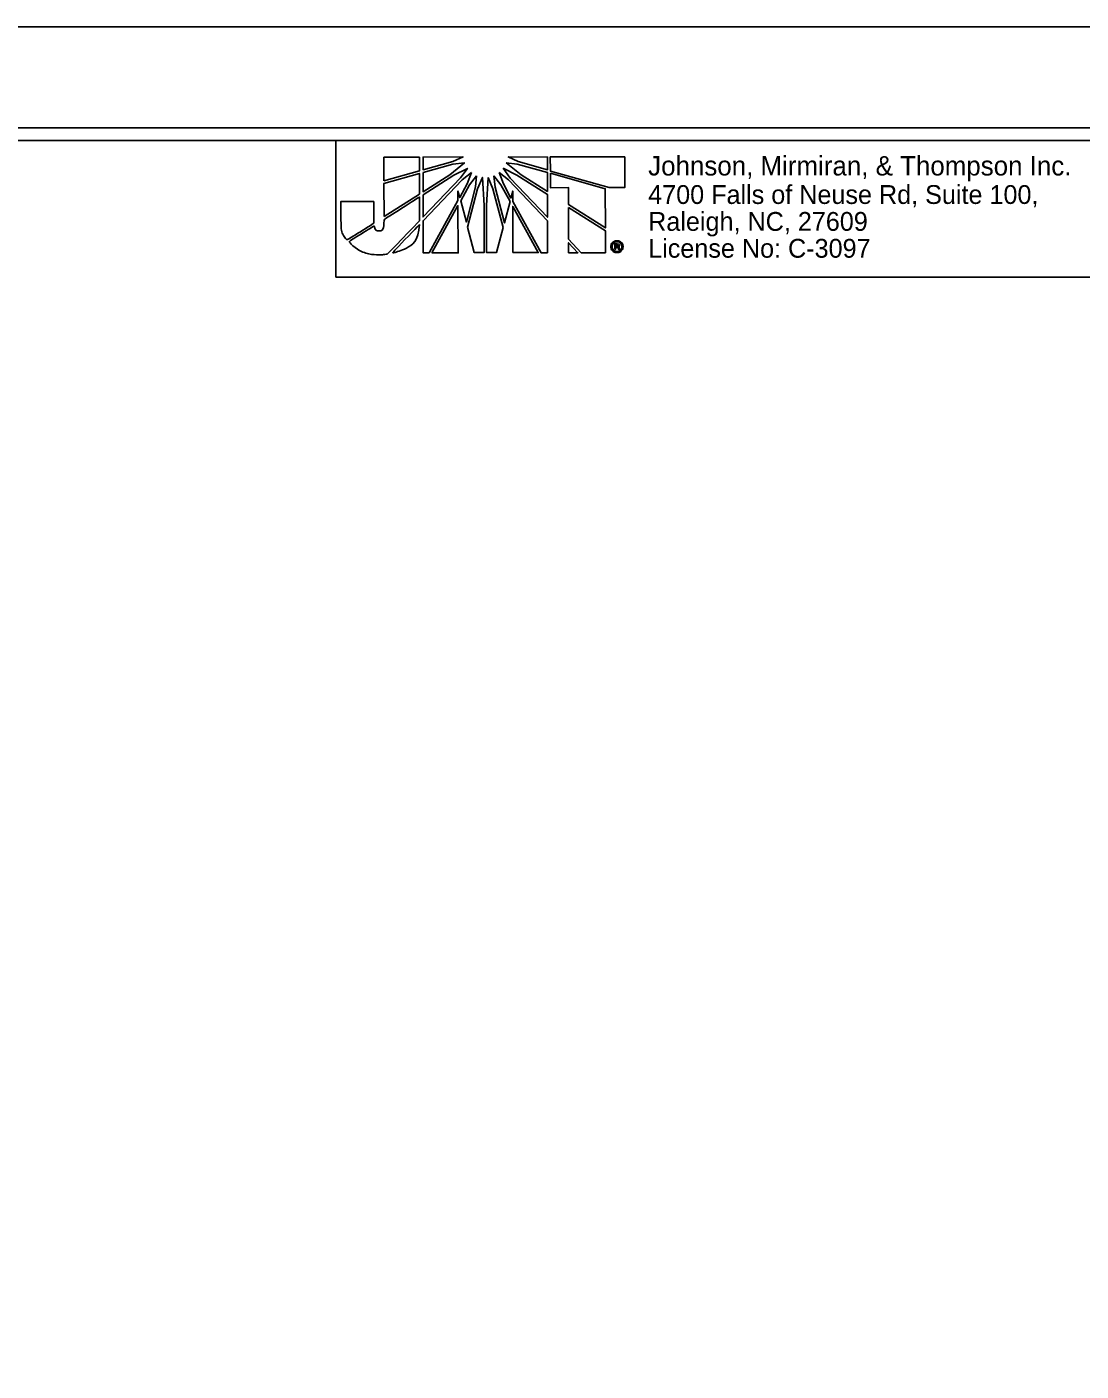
# Model space of a CAD drawing. Extents: x 1639431 to 1642602, y 841916 to 843940.
# Drawn here: x 1641459.6 to 1641668.2, y 842745.3 to 843011.3 of the extents above; entities that cross this region are included whole.
import ezdxf

# ---------------------------------------------------------------- set-up
doc = ezdxf.new("R2010")
doc.units = 0
for name, color, linetype in [('Prop Dimension Text', 7, 'Continuous'), ('Sheet Plan CELL', 7, 'Continuous'), ('Sheet Plot Border Inside CELL', 7, 'Continuous'), ('Sheet Plot Border Outside CELL', 7, 'Continuous')]:
    doc.layers.add(name, color=color, linetype=linetype)

msp = doc.modelspace()

# ---------------------------------------------------------------- linework, layer by layer
at = {"layer": 'Prop Dimension Text'}
for p, q in [((1641537.24, 842985.52), (1641530.22, 842985.51)), ((1641530.22, 842985.51), (1641530.22, 842980.85)), ((1641537.24, 842982.81), (1641537.24, 842985.52)), ((1641545.87, 842985.56), (1641537.97, 842985.55)), ((1641537.97, 842985.55), (1641537.97, 842983.04)), ((1641543.86, 842984.67), (1641545.87, 842985.56)), ((1641562.6, 842985.54), (1641554.81, 842985.57)), ((1641554.81, 842985.57), (1641556.79, 842984.64)), ((1641562.6, 842983.02), (1641562.6, 842985.54)), ((1641577.91, 842985.59), (1641563.14, 842985.58)), ((1641563.14, 842985.58), (1641563.15, 842982.87)), ((1641577.91, 842979.54), (1641577.91, 842985.59)), ((1641530.22, 842980.85), (1641537.24, 842982.81)), ((1641537.97, 842983.04), (1641543.86, 842984.67)), ((1641543.86, 842984.12), (1641537.97, 842982.49)), ((1641537.97, 842982.49), (1641537.98, 842978.69)), ((1641543.24, 842982.04), (1641546.15, 842984.4)), ((1641546.15, 842984.4), (1641543.86, 842984.12)), ((1641546.73, 842983.31), (1641544.06, 842981.95)), ((1641545.38, 842981.41), (1641546.73, 842983.31)), ((1641547.54, 842982.47), (1641545.68, 842981.03)), ((1641546.69, 842980.22), (1641547.54, 842982.47)), ((1641552.99, 842982.47), (1641553.85, 842980.23)), ((1641554.85, 842981.04), (1641552.99, 842982.47)), ((1641553.81, 842983.32), (1641555.17, 842981.39)), ((1641556.52, 842981.97), (1641553.81, 842983.32)), ((1641554.42, 842984.41), (1641557.37, 842982)), ((1641556.59, 842984.13), (1641554.42, 842984.41)), ((1641562.6, 842982.48), (1641556.59, 842984.13)), ((1641556.79, 842984.64), (1641562.6, 842983.02)), ((1641562.56, 842978.76), (1641562.6, 842982.48)), ((1641563.15, 842982.87), (1641563.15, 842982.78)), ((1641563.15, 842982.78), (1641574.77, 842979.54)), ((1641537.24, 842982.3), (1641530.22, 842980.32)), ((1641530.22, 842980.32), (1641530.23, 842973.77)), ((1641537.25, 842978.23), (1641537.24, 842982.3)), ((1641537.98, 842978.69), (1641543.24, 842982.04)), ((1641544.06, 842981.95), (1641537.98, 842978.08)), ((1641537.98, 842973.7), (1641545.38, 842981.41)), ((1641545.68, 842981.03), (1641537.98, 842972.96)), ((1641545.22, 842977.54), (1641546.69, 842980.22)), ((1641547.16, 842980.06), (1641545.42, 842976.88)), ((1641548.55, 842981.84), (1641547.16, 842980.06)), ((1641548.36, 842979.68), (1641548.55, 842981.84)), ((1641549.71, 842981.53), (1641548.75, 842979.28)), ((1641550.02, 842975.99), (1641549.71, 842981.53)), ((1641550.87, 842981.53), (1641550.51, 842975.99)), ((1641551.8, 842979.29), (1641550.87, 842981.53)), ((1641551.99, 842981.85), (1641552.23, 842979.6)), ((1641553.35, 842980.06), (1641551.99, 842981.85)), ((1641555.17, 842976.78), (1641553.35, 842980.06)), ((1641553.85, 842980.23), (1641555.36, 842977.44)), ((1641562.57, 842972.91), (1641554.85, 842981.04)), ((1641555.17, 842981.39), (1641562.57, 842973.64)), ((1641562.56, 842978.14), (1641556.52, 842981.97)), ((1641557.37, 842982), (1641562.56, 842978.76)), ((1641563.15, 842982.37), (1641563.15, 842982.32)), ((1641574.03, 842979.27), (1641563.15, 842982.37)), ((1641563.15, 842982.32), (1641563.15, 842979.49)), ((1641530.23, 842973.77), (1641537.25, 842978.23)), ((1641537.98, 842978.08), (1641537.98, 842973.7)), ((1641544.87, 842976.96), (1641544.87, 842978.82)), ((1641544.87, 842978.82), (1641545.22, 842977.54)), ((1641546.54, 842972.67), (1641548.36, 842979.68)), ((1641548.75, 842979.28), (1641546.78, 842971.69)), ((1641553.82, 842971.58), (1641551.8, 842979.29)), ((1641552.23, 842979.6), (1641554.05, 842972.51)), ((1641555.36, 842977.44), (1641555.71, 842978.83)), ((1641555.71, 842978.83), (1641555.72, 842976.78)), ((1641562.57, 842973.64), (1641562.56, 842978.14)), ((1641563.15, 842979.49), (1641566.75, 842979.5)), ((1641566.75, 842979.5), (1641566.76, 842976.13)), ((1641574.04, 842971.52), (1641574.03, 842979.27)), ((1641574.77, 842979.54), (1641577.91, 842979.54)), ((1641539.15, 842966.59), (1641544.87, 842976.96)), ((1641544.87, 842975.95), (1641539.69, 842966.59)), ((1641544.93, 842966.59), (1641544.87, 842975.95)), ((1641545.42, 842976.88), (1641546.54, 842972.67)), ((1641550.02, 842966.63), (1641550.02, 842975.99)), ((1641550.51, 842975.99), (1641550.52, 842966.63)), ((1641554.05, 842972.51), (1641555.17, 842976.78)), ((1641555.72, 842976.78), (1641561.33, 842966.61)), ((1641560.75, 842966.64), (1641555.72, 842975.77)), ((1641555.72, 842975.77), (1641555.73, 842966.64)), ((1641566.76, 842976.13), (1641574.04, 842971.52)), ((1641566.76, 842975.55), (1641566.76, 842969.27)), ((1641574.04, 842970.98), (1641566.76, 842975.55)), ((1641537.98, 842972.96), (1641537.99, 842966.59)), ((1641562.57, 842966.61), (1641562.57, 842972.91)), ((1641546.78, 842971.69), (1641548.1, 842966.63)), ((1641552.47, 842966.64), (1641553.82, 842971.58)), ((1641566.76, 842969.27), (1641569.28, 842966.62)), ((1641574.04, 842966.62), (1641574.04, 842970.98)), ((1641537.99, 842966.59), (1641539.15, 842966.59)), ((1641539.69, 842966.59), (1641544.93, 842966.59)), ((1641548.1, 842966.63), (1641550.02, 842966.63)), ((1641550.52, 842966.63), (1641552.47, 842966.64)), ((1641555.73, 842966.64), (1641560.75, 842966.64)), ((1641561.33, 842966.61), (1641562.57, 842966.61)), ((1641568.59, 842966.62), (1641566.76, 842968.58)), ((1641566.76, 842968.58), (1641566.77, 842966.61)), ((1641566.77, 842966.61), (1641568.59, 842966.62)), ((1641569.28, 842966.62), (1641574.04, 842966.62)), ((1641575.89, 842967.29), (1641575.89, 842968.36)), ((1641575.89, 842968.36), (1641576.33, 842968.36)), ((1641576.13, 842967.29), (1641575.89, 842967.29)), ((1641576.33, 842968.15), (1641576.13, 842968.15)), ((1641576.13, 842968.15), (1641576.13, 842967.9)), ((1641576.13, 842967.9), (1641576.33, 842967.9)), ((1641576.33, 842967.71), (1641576.13, 842967.71)), ((1641576.13, 842967.71), (1641576.13, 842967.29)), ((1641576.33, 842968.99), (1641576.33, 842968.77)), ((1641576.33, 842968.77), (1641576.33, 842968.99)), ((1641576.33, 842968.36), (1641576.33, 842968.15)), ((1641576.33, 842968.15), (1641576.33, 842968.36)), ((1641576.33, 842968.36), (1641576.4, 842968.36)), ((1641576.36, 842968.15), (1641576.33, 842968.15)), ((1641576.33, 842967.9), (1641576.33, 842967.71)), ((1641576.33, 842967.71), (1641576.33, 842967.9)), ((1641576.33, 842967.9), (1641576.34, 842967.9)), ((1641576.34, 842967.71), (1641576.33, 842967.71)), ((1641576.33, 842966.87), (1641576.33, 842966.63)), ((1641576.33, 842966.63), (1641576.33, 842966.87)), ((1641576.33, 842966.87), (1641576.34, 842966.87)), ((1641576.34, 842966.63), (1641576.33, 842966.63))]:
    msp.add_line(p, q, dxfattribs=at)
msp.add_lwpolyline([(1641520.72, 842961.76), (1641670.75, 842961.76), (1641670.75, 842988.83), (1641520.72, 842988.83)], close=True, dxfattribs=at)
for points in [[(1641530.22, 842980.85), (1641537.24, 842982.81), (1641537.24, 842985.52), (1641530.22, 842985.51), (1641530.22, 842980.85)], [(1641543.86, 842984.67), (1641545.87, 842985.56), (1641537.97, 842985.55), (1641537.97, 842983.04), (1641543.86, 842984.67)], [(1641556.79, 842984.64), (1641562.6, 842983.02), (1641562.6, 842985.54), (1641554.81, 842985.57), (1641556.79, 842984.64)], [(1641577.91, 842985.59), (1641563.14, 842985.58), (1641563.15, 842982.87), (1641563.15, 842982.78), (1641574.77, 842979.54), (1641577.91, 842979.54), (1641577.91, 842985.59)], [(1641537.97, 842982.49), (1641537.98, 842978.69), (1641543.24, 842982.04), (1641546.15, 842984.4), (1641543.86, 842984.12), (1641537.97, 842982.49)], [(1641537.98, 842978.08), (1641537.98, 842973.7), (1641545.38, 842981.41), (1641546.73, 842983.31), (1641544.06, 842981.95), (1641537.98, 842978.08)], [(1641547.54, 842982.47), (1641545.68, 842981.03), (1641537.98, 842972.96), (1641537.99, 842966.59), (1641539.15, 842966.59), (1641544.87, 842976.96), (1641544.87, 842978.82), (1641545.22, 842977.54), (1641546.69, 842980.22), (1641547.54, 842982.47)], [(1641552.99, 842982.47), (1641553.85, 842980.23), (1641555.36, 842977.44), (1641555.71, 842978.83), (1641555.72, 842976.78), (1641561.33, 842966.61), (1641562.57, 842966.61), (1641562.57, 842972.91), (1641554.85, 842981.04), (1641552.99, 842982.47)], [(1641553.81, 842983.32), (1641555.17, 842981.39), (1641562.57, 842973.64), (1641562.56, 842978.14), (1641556.52, 842981.97), (1641553.81, 842983.32)], [(1641554.42, 842984.41), (1641557.37, 842982), (1641562.56, 842978.76), (1641562.6, 842982.48), (1641556.59, 842984.13), (1641554.42, 842984.41)], [(1641530.23, 842973.77), (1641537.25, 842978.23), (1641537.24, 842982.3), (1641530.22, 842980.32), (1641530.23, 842973.77)], [(1641548.55, 842981.84), (1641547.16, 842980.06), (1641545.42, 842976.88), (1641546.54, 842972.67), (1641548.36, 842979.68), (1641548.55, 842981.84)], [(1641548.75, 842979.28), (1641546.78, 842971.69), (1641548.1, 842966.63), (1641550.02, 842966.63), (1641550.02, 842975.99), (1641549.71, 842981.53), (1641548.75, 842979.28)], [(1641550.87, 842981.53), (1641550.51, 842975.99), (1641550.52, 842966.63), (1641552.47, 842966.64), (1641553.82, 842971.58), (1641551.8, 842979.29), (1641550.87, 842981.53)], [(1641551.99, 842981.85), (1641552.23, 842979.6), (1641554.05, 842972.51), (1641555.17, 842976.78), (1641553.35, 842980.06), (1641551.99, 842981.85)], [(1641563.15, 842982.37), (1641563.15, 842982.32), (1641563.15, 842979.49), (1641566.75, 842979.5), (1641566.76, 842976.13), (1641574.04, 842971.52), (1641574.03, 842979.27), (1641563.15, 842982.37)], [(1641539.69, 842966.59), (1641544.93, 842966.59), (1641544.87, 842975.95), (1641539.69, 842966.59)], [(1641555.73, 842966.64), (1641560.75, 842966.64), (1641555.72, 842975.77), (1641555.73, 842966.64)], [(1641566.76, 842975.55), (1641566.76, 842969.27), (1641569.28, 842966.62), (1641574.04, 842966.62), (1641574.04, 842970.98), (1641566.76, 842975.55), (1641566.76, 842975.55)], [(1641566.77, 842966.61), (1641566.77, 842966.61), (1641568.59, 842966.62), (1641566.76, 842968.58), (1641566.77, 842966.61)], [(1641576.8, 842967.54), (1641576.8, 842967.48), (1641576.81, 842967.44), (1641576.81, 842967.4), (1641576.84, 842967.29), (1641576.61, 842967.29)]]:
    msp.add_lwpolyline(points, dxfattribs=at)
for points, degree in [([(1641529.22, 842970.93), (1641528.81, 842970.93), (1641528.45, 842971.17), (1641528.3, 842971.94), (1641528.3, 842971.94), (1641523.26, 842968.82), (1641523.26, 842968.82), (1641524.81, 842967.19), (1641527.29, 842966.22), (1641529.39, 842966.22), (1641529.94, 842966.22), (1641530.35, 842966.27), (1641530.93, 842966.38), (1641530.93, 842966.38), (1641537.25, 842972.92), (1641537.25, 842972.92), (1641537.25, 842972.92), (1641537.25, 842977.65), (1641537.25, 842977.65), (1641537.25, 842977.65), (1641530.23, 842973.18), (1641530.23, 842973.18), (1641530.23, 842971.41), (1641529.8, 842970.93), (1641529.22, 842970.93)], 3), ([(1641529.22, 842970.93), (1641528.81, 842970.93), (1641528.45, 842971.17), (1641528.3, 842971.94), (1641528.3, 842971.94), (1641523.26, 842968.82), (1641523.26, 842968.82), (1641524.81, 842967.19), (1641527.29, 842966.22), (1641529.39, 842966.22), (1641529.94, 842966.22), (1641530.35, 842966.27), (1641530.93, 842966.38), (1641530.93, 842966.38), (1641537.25, 842972.92), (1641537.25, 842972.92), (1641537.25, 842972.92), (1641537.25, 842977.65), (1641537.25, 842977.65), (1641537.25, 842977.65), (1641530.23, 842973.18), (1641530.23, 842973.18), (1641530.23, 842971.41), (1641529.8, 842970.93), (1641529.22, 842970.93)], 3), ([(1641528.21, 842976.78), (1641528.21, 842976.78), (1641521.71, 842976.78), (1641521.71, 842976.78), (1641521.71, 842976.78), (1641521.72, 842972.71), (1641521.72, 842972.71), (1641521.72, 842972.71), (1641521.72, 842972.28), (1641521.72, 842972.28), (1641521.72, 842971.01), (1641522.13, 842970), (1641522.88, 842969.16), (1641522.88, 842969.16), (1641528.22, 842972.4), (1641528.22, 842972.49), (1641528.22, 842972.49), (1641528.21, 842976.78), (1641528.21, 842976.78)], 3), ([(1641537.25, 842972.18), (1641537.25, 842972.18), (1641531.79, 842966.53), (1641531.79, 842966.53), (1641534.46, 842967.2), (1641537.13, 842968.97), (1641537.25, 842972.18)], 3), ([(1641576.33, 842966.63), (1641576.01, 842966.63), (1641575.72, 842966.75), (1641575.49, 842966.98), (1641575.26, 842967.21), (1641575.14, 842967.49), (1641575.14, 842967.82), (1641575.14, 842968.15), (1641575.25, 842968.44), (1641575.49, 842968.65), (1641575.72, 842968.88), (1641576, 842968.99), (1641576.33, 842968.99)], 3), ([(1641576.33, 842968.77), (1641576.06, 842968.77), (1641575.84, 842968.68), (1641575.65, 842968.5), (1641575.47, 842968.32), (1641575.37, 842968.09), (1641575.37, 842967.82), (1641575.37, 842967.56), (1641575.47, 842967.32), (1641575.66, 842967.14), (1641575.84, 842966.95), (1641576.07, 842966.87), (1641576.33, 842966.87)], 3), ([(1641576.33, 842968.99), (1641576.66, 842968.99), (1641576.94, 842968.88), (1641577.18, 842968.65), (1641577.41, 842968.44), (1641577.53, 842968.16), (1641577.53, 842967.82)], 3), ([(1641576.34, 842966.87), (1641576.6, 842966.87), (1641576.83, 842966.95), (1641577.01, 842967.14), (1641577.2, 842967.33), (1641577.29, 842967.56), (1641577.29, 842967.82), (1641577.29, 842968.09), (1641577.2, 842968.32), (1641577.01, 842968.51), (1641576.83, 842968.68), (1641576.6, 842968.77), (1641576.33, 842968.77)], 3), ([(1641576.34, 842967.9), (1641576.49, 842967.9), (1641576.57, 842967.95), (1641576.57, 842968.04), (1641576.57, 842968.12), (1641576.5, 842968.15), (1641576.36, 842968.15)], 3), ([(1641577.53, 842967.82), (1641577.53, 842967.49), (1641577.41, 842967.21), (1641577.19, 842966.97), (1641576.95, 842966.75), (1641576.67, 842966.63), (1641576.34, 842966.63)], 3), ([(1641576.52, 842967.67), (1641576.49, 842967.69), (1641576.44, 842967.71), (1641576.34, 842967.71)], 2), ([(1641576.4, 842968.36), (1641576.67, 842968.36), (1641576.81, 842968.25), (1641576.81, 842968.04), (1641576.81, 842967.94), (1641576.77, 842967.86), (1641576.68, 842967.8)], 3), ([(1641576.61, 842967.29), (1641576.58, 842967.34), (1641576.56, 842967.4), (1641576.56, 842967.48), (1641576.56, 842967.58), (1641576.55, 842967.64), (1641576.52, 842967.67)], 3), ([(1641576.68, 842967.8), (1641576.75, 842967.76), (1641576.79, 842967.68), (1641576.8, 842967.54)], 2)]:
    msp.add_open_spline(points, degree=degree, dxfattribs=at)
at = {"layer": 'Sheet Plan CELL'}
for points in [[(1640370.79, 841938.82), (1640370.76, 842988.79), (1641670.75, 842988.83), (1641670.76, 842838.77), (1641870.8, 842838.76), (1641870.8, 841938.82)], [(1641870.83, 842988.82), (1640370.79, 842988.82), (1640370.79, 841938.82), (1641870.8, 841938.82)]]:
    msp.add_lwpolyline(points, close=True, dxfattribs=at)
at = {"layer": 'Sheet Plot Border Inside CELL'}
msp.add_lwpolyline([(1640217.3, 841936.31), (1641883.29, 841936.32), (1641883.3, 842991.31), (1640217.3, 842991.31)], close=True, dxfattribs=at)
at = {"layer": 'Sheet Plot Border Outside CELL'}
msp.add_lwpolyline([(1640204.3, 841916.31), (1641887.8, 841916.31), (1641887.8, 843011.31), (1640204.3, 843011.31)], close=True, dxfattribs=at)
msp.add_lwpolyline([(1640204.3, 841916.31), (1641887.8, 841916.31), (1641887.8, 843011.31), (1640204.3, 843011.31)], close=True, dxfattribs=at)

# ---------------------------------------------------------------- texts
at = {"layer": 'Prop Dimension Text'}
for s, height, p in [('Johnson, Mirmiran, & Thompson Inc.', 3.8334, (1641582.51, 842981.9)), ('4700 Falls of Neuse Rd, Suite 100, ', 3.7239, (1641582.51, 842976.27)), ('Raleigh, NC, 27609', 3.7239, (1641582.51, 842970.95)), ('License No: C-3097', 3.7239, (1641582.51, 842965.63))]:
    msp.add_text(s, height=height, dxfattribs=at).set_placement(p)

doc.saveas('drawing.dxf')
